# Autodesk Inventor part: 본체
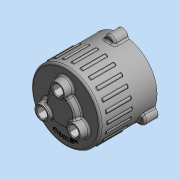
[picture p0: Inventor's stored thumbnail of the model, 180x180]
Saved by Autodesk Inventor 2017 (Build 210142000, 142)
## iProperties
Created: 2015-11
Part Number: 본체
Document SubType Name: 모델링
Designer: mdu
Material: 일반
Density: 1 g/cm^3
Mass: 250.598 g
Surface Area: 733.607 cm^2
Volume: 250.598 cm^3
Appearance: 기본값
변환 표준: STEP AP214IS
파일 이름: C:\Users\SeoGD\Desktop\?쒗뿕\紐몄껜.stp
전처리기: Build: 253, Release: 2010 SP1 - Date: Wed 07/29/2009
전송 단위: 밀리미터
불확실성: 0.01
Author: mdu
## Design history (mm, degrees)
sketch "스케치2"
  geometry: C1 r 52 at (0, 0); 1 further point
  constraints: 1 centre point, 1 coincident
  dimensions: "d9" = 104 diameter of C1
extrude "돌출2" new body sketch "스케치2" distance "d10" = 85.5; taper "d11" = 0 deg
feature "쉘1" dims "d12" = 7
sketch "스케치3" dims "d13" = 55
  geometry: C1 r 7.5 at (0, 27.5); C2 r 12.5 at (0, 27.5); 2 further points
  constraints: 2 centre point, 2 coincident, 2 vertical alignment, 2 other
  dimensions: "d14" = 15 diameter of C1; "d15" = 25 diameter of C2
extrude "돌출3" join sketch "스케치3" distance "d16" = 12; taper "d17" = -10 deg
sketch "스케치4"
  geometry: L1 (0, 0)-(0, 93.5); L2 (0, 71.5)-(12.624, 71.5); L3 (-45, 78.5)-(45, 78.5) reference; L4 (-52, 85.5)-(52, 85.5) reference; L5 (12.624, 71.5)-(14.5, 78.5); L6 (20.381, 93.5)-(0, 93.5); L7 (25, 85.5)-(14.5, 78.5); L8 (25, 85.5)-(20.381, 93.5)
  constraints: 12 end point, 3 point on line, 1 perpendicular, 1 vertical
  dimensions: "d35" = 105 deg angle of L5 L3; "d36" = 7 distance between parallel lines of L2 L3; "d37" = 8 distance between parallel lines of L6 L4; "d51" = 29 diameter of L5.end L1; "d92" = 50 diameter of L7.start L1; "d93" = 120 deg angle of L6 L8
revolve "회전1" sketch "스케치4" stored, may be unused: angle "d38" = 90 deg
hole "구멍2" diameter "d20" = 15; stored, may be unused: countersink angle "d24" = 90 deg, drill point angle "d26" = 118 deg; dims "d18" = 10, "d19" = 10, "d21" = 6, "d22" = 4, "d23" = 2, "d25" = 15
chamfer "모따기1" distance "d27" = 1; stored, may be unused: second distance "d28" = 2, angle "d29" = 45 deg
hole "구멍3" diameter "d41" = 15; stored, may be unused: countersink angle "d45" = 90 deg, drill point angle "d47" = 0 deg; dims "d42" = 6, "d43" = 22, "d44" = 13, "d46" = 16, "d96" = 10, "d97" = 10
chamfer "모따기2" distance "d48" = 1; stored, may be unused: second distance "d49" = 2, angle "d50" = 45 deg
fillet "모깎기1" dims "d52" = 3
fillet "모깎기2" dims "d53" = 3, "d72" = 0.2, "d94" = 2
sketch "스케치5"
  geometry: A1 r 52 centre (0, 0) between (52, 0) and (-8.472, 51.305) reference; A2 r 8.5 centre (0, 52) between (8.472, 51.305) and (-8.472, 51.305); 1 further point
  constraints: 5 point on circle, 1 centre point, 1 horizontal alignment
  dimensions: "d54" = 90 deg dimension on point (0, 0) A2.centre A1.start; "d55" = 52 distance of A2.centre point (0, 0); "d56" = 17 diameter of A2
extrude "돌출4" join sketch "스케치5" distance "d57" = 20; taper "d58" = 0 deg
fillet "모깎기3" dims "d59" = 3
hole "구멍4" diameter "d62" = 4.134; stored, may be unused: countersink angle "d66" = 90 deg, drill point angle "d68" = 118 deg; dims "d60" = 10, "d61" = 10, "d63" = 12, "d64" = 22, "d65" = 13, "d67" = 15
sketch "스케치6"
  geometry: C1 r 49 at (0, 0) reference; C2 r 42.5 at (0, 0); 1 further point
  constraints: 1 centre point, 1 coincident, 1 other
  dimensions: "d73" = 85 diameter of C2
feature "엠보싱1" sketch "스케치6" dims "d74" = 0.5, "d75" = 0
node "작업 평면1"
sketch "스케치7"
  geometry: A1 r 52 centre (0, 0) between (4.478, 51.807) and (-4.478, 51.807) reference; A2 r 3 centre (0, 50) between (2.28, 51.95) and (-2.28, 51.95); 1 further point
  constraints: 4 point on circle, 1 centre point, 1 vertical alignment
  dimensions: "d77" = 3 radius of A2; "d91" = 50 distance of point (0, 0) A2.centre
extrude "돌출5" join sketch "스케치7" distance "d79" = 38; taper "d80" = 0 deg
fillet "모깎기4" dims "d81" = 1
fillet "모깎기5" dims "d82" = 1
node "솔리드1"
node "솔리드 본체"
node "곡면 본체"
pattern_circular "원형 패턴1" dims angle "d31" = 360 deg
pattern_circular "원형 패턴2" dims angle "d70" = 360 deg
pattern_circular "원형 패턴3" dims angle "d84" = 360 deg
node "솔리드2"
